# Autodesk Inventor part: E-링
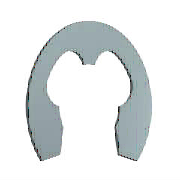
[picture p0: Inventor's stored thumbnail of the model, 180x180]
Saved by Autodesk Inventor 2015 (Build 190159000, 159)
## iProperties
IsCustomPart: 1
Created: 2012-02
Part Number: E-링
Material: 강철, 연강
Description: 일반용 테이퍼 및 줄어든 횡단면 리테이닝 링 - E-링 외부 시리즈 3CM1 리테이닝 링
Document SubType Name: Modeling
Standard: ANSI B27.7
Designer: mduedu
Standard Revision: 1999
Standards Organization: ANSI
Language: ko-KR
Size Designation: 6
Categories: <MemberInstance><Categories><Category DisplayName="샤프트 부품" InternalName="7f7aeb1f-a693-4053-b835-cee3144e0d98" Mnemonic="SHFT"><Category DisplayName="써클립" Inter
Density: 1 g/cm^3
Appearance: 파란색 - 벽 페인트 - 광택
Author: mduedu
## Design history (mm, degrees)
sketch "스케치1"
  geometry: L1 (-0.485, 0.024)-(0, 0.024) reference; L2 (-3.206, 0)-(3.486, 0) reference; L3 (-2.223, -3.946)-(2.223, -3.946); L4 (0, 1.949)-(0, -3.479) reference; L5 (-2.91, -2.006)-(-2.435, -2.006); L6 (-0.485, -0.066)-(-0.485, 0.405); L7 (0, 2.574)-(2.53, 2.574); L8 (-2.223, -3.946)-(-3.022, -6.291); L9 (0, -0.551)-(-1.278, -0.551); L10 (2.223, -3.946)-(3.022, -6.291); L11 (2.91, -2.006)-(2.435, -2.006); L12 (0.485, -0.066)-(0.485, 0.405); C1 r 3 at (0, -2.976); A1 r 2.425 centre (0, -2.976) between (-2.297, -2.199) and (-2.223, -3.946); A2 r 0.485 centre (0, -0.066) between (-0.485, -0.066) and (0.485, -0.066); A3 r 5.55 centre (0, -2.976) between (4.27, -6.521) and (-4.27, -6.521); A4 r 3.88 centre (0, -2.976) between (-0.97, 0.78) and (-3.424, -1.15); A5 r 0.388 centre (-0.873, 0.405) between (-0.485, 0.405) and (-0.97, 0.78); A6 r 0.582 centre (-2.91, -1.424) between (-3.424, -1.15) and (-2.91, -2.006); A7 r 0.145 centre (-2.435, -2.152) between (-2.297, -2.199) and (-2.435, -2.006); A8 r 0.727 centre (-3.711, -6.057) between (-4.27, -6.521) and (-3.022, -6.291); A9 r 0.727 centre (3.711, -6.057) between (3.022, -6.291) and (4.27, -6.521); A10 r 2.425 centre (0, -2.976) between (2.223, -3.946) and (2.297, -2.199); A11 r 0.145 centre (2.435, -2.152) between (2.435, -2.006) and (2.297, -2.199); A12 r 0.582 centre (2.91, -1.424) between (2.91, -2.006) and (3.424, -1.15); A13 r 3.88 centre (0, -2.976) between (3.424, -1.15) and (0.97, 0.78); A14 r 0.388 centre (0.873, 0.405) between (0.97, 0.78) and (0.485, 0.405); 1 further point
  constraints: 30 point on circle, 20 end point, 15 centre point, 13 symmetric about line, 12 tangent, 8 point on line, 4 parallel, 2 coincident, 2 horizontal, 1 concentric, 1 perpendicular, 1 vertical alignment, 9 other
  dimensions: "d0" = 6 diameter of C1 (= WD); "d3" = 0.97 distance from line of A1.centre L3 (= 0.2 x ND); "d4" = 0.485 radius of A2 (= 0.1 x ND); "d5" = 11.1 diameter of A3 (= SD2); "d8" = 3.88 radius of A4 (= 0.8 x ND); "d9" = 0.97 distance from line of A1.centre L5 (= 0.2 x ND); "d10" = 0.388 radius of A5 (= 0.08 x ND); "d11" = 0.582 radius of A6 (= 0.12 x ND); "d12" = 0.1455 radius of A7 (= 0.03 x ND); "d13" = 0.7275 radius of A8 (= 0.15 x ND); "d14" = 2.425 distance from line of A1.centre L9 (= 0.5 x ND); "d15" = 2.425 radius of A1 (= 0.5 x ND)
extrude "본체" new body sketch "스케치1" distance "d16" = 0.6 (= SD); taper "d17" = 0 deg
workaxis "Work Axis1"
workaxis "Work Axis2"
workplane "Work Plane1"
body "Solid1"
other parameters: "ND" = 4.85 [user parameter; used in 14 equation terms], "SD" = 0.6 [user parameter; used in 1 equation term], "WD" = 6 (= WDMIN) [user parameter; used in 1 equation term], "d1" = 7.76 (= 1.6 x ND), "d2" = 4.85 (= ND), "SD2" = 11.1 [user parameter; used in 1 equation term], "d6" = 4.85 (= ND), "d7" = 0.7275 (= 0.15 x ND), "d18" = 0, "d19" = 0, "d27" = 0, "d28" = 0, "WDMIN" = 6 [user parameter; used in 1 equation term], "SNB" = 0.7 [user parameter], "WDMAX" = 7 [user parameter], "BUBRMI" = 1.2 [user parameter]
